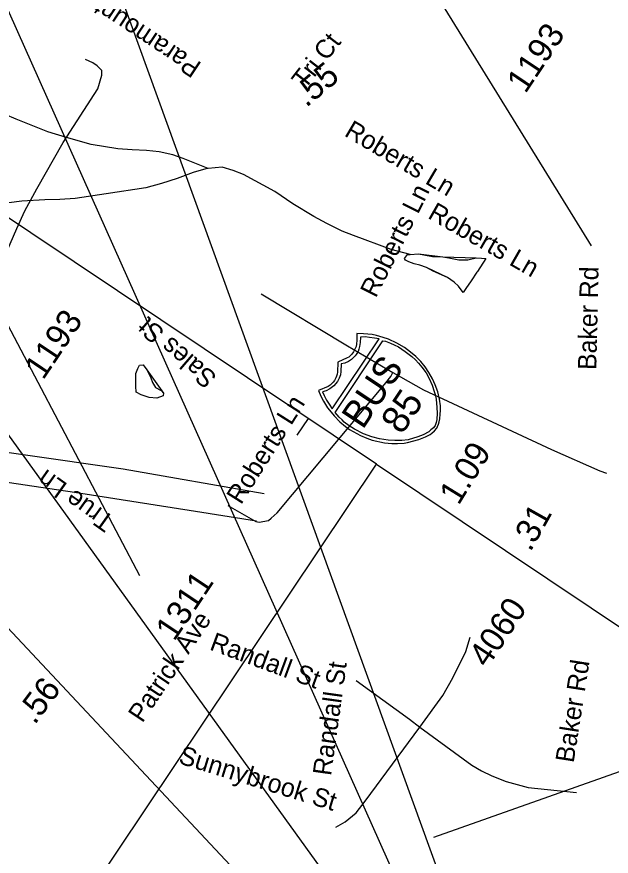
# Model space of a CAD drawing. Extents: x 1716282 to 1717158, y 799307 to 801078.
# Drawn here: x 1716895.7 to 1716939.9, y 800803.5 to 800865.9 of the extents above; entities that cross this region are included whole.
import ezdxf

# ---------------------------------------------------------------- set-up
doc = ezdxf.new("R2010")
doc.units = 0
for name, color, linetype in [('Exist Hydrographic Misc Water Feature', 7, 'Continuous'), ('Exist Road Non-System Type 51', 7, 'Continuous'), ('Exist Road Non-System Type 51 Label', 7, 'Continuous'), ('Exist Road Primary Interstate Mileage Hundredths English Label', 7, 'Continuous'), ('Exist Road Primary Interstate Service Mileage Label', 7, 'Continuous'), ('Exist Road Primary Interstate Shield CELL', 7, 'Continuous'), ('Exist Road Primary Interstate Shield Number Label', 7, 'Continuous'), ('Exist Road Primary Interstate Structure Culvert Number Label', 7, 'Continuous'), ('Exist Road Primary Interstate Structure Ovrhead Sign CELL', 7, 'Continuous'), ('Exist Road Primary US Structure Standard Bridge Number Label', 7, 'Continuous'), ('Exist Road Secondary Mileage Hundredths English Label', 7, 'Continuous'), ('Exist Road Secondary Mileage Tenths English Label', 7, 'Continuous'), ('Exist Road Secondary Structure Standard Bridge Number Label', 7, 'Continuous'), ('Exist Road Secondary Type 51 Attributed', 7, 'Continuous'), ('Exist Road Secondary Type 51 Label', 7, 'Continuous'), ('Exist Road Secondary Type 51 Number Label', 7, 'Continuous'), ('Prop DSN Text', 7, 'Continuous'), ('Prop Road Primary US Projected', 7, 'Continuous')]:
    doc.layers.add(name, color=color, linetype=linetype)

msp = doc.modelspace()

# ---------------------------------------------------------------- linework, layer by layer
at = {"layer": 'Exist Hydrographic Misc Water Feature'}
for points in [[(1716909.97, 800854.633), (1716909.089, 800854.988), (1716908.12, 800855.37), (1716907.335, 800855.66), (1716906.315, 800855.865), (1716905.375, 800855.979), (1716904.322, 800856.032), (1716903.244, 800856.101), (1716901.285, 800856.421), (1716899.432, 800856.948), (1716898.061, 800857.359), (1716895.691, 800858.311), (1716894.897, 800858.641), (1716894.273, 800858.961)], [(1716909.97, 800854.633), (1716909.784, 800854.618), (1716908.856, 800854.339), (1716907.668, 800853.886), (1716906.506, 800853.521), (1716905.336, 800853.197), (1716902.394, 800852.747), (1716900.097, 800852.418), (1716898.947, 800852.328), (1716897.844, 800852.308), (1716896.128, 800852.215), (1716895.153, 800852.073), (1716894.565, 800852.087), (1716893.343, 800852.15), (1716892.531, 800852.246), (1716892.138, 800852.34)], [(1716924.968, 800848.253), (1716923.565, 800848.614), (1716920.759, 800849.651), (1716919.927, 800849.975), (1716918.775, 800850.551), (1716917.822, 800851.059), (1716916.265, 800852.019), (1716914.923, 800852.935), (1716912.58, 800854.185), (1716911.834, 800854.482), (1716911.017, 800854.725), (1716909.97, 800854.633)], [(1716929.933, 800846.932), (1716929.491, 800846.285), (1716929.098, 800845.71), (1716928.902, 800845.423), (1716928.562, 800845.902), (1716928.235, 800846.195), (1716927.733, 800846.54), (1716927.116, 800846.819), (1716926.683, 800847.009), (1716926.196, 800847.272), (1716925.682, 800847.448), (1716925.266, 800847.556), (1716924.864, 800847.69), (1716924.633, 800847.814), (1716924.546, 800847.942), (1716924.782, 800848.238), (1716924.968, 800848.253)], [(1716929.933, 800846.932), (1716929.491, 800846.285), (1716929.098, 800845.71), (1716928.902, 800845.423), (1716928.562, 800845.902), (1716928.235, 800846.195), (1716927.733, 800846.54), (1716926.196, 800847.272), (1716925.682, 800847.448), (1716925.266, 800847.556), (1716924.864, 800847.69), (1716924.633, 800847.814), (1716924.546, 800847.942), (1716924.782, 800848.238), (1716924.968, 800848.253)], [(1716924.968, 800848.253), (1716925.588, 800848.286), (1716926.623, 800848.104), (1716927.404, 800848.065), (1716927.854, 800848.003), (1716928.592, 800847.849), (1716929.259, 800847.85), (1716929.881, 800847.988), (1716930.259, 800847.975), (1716930.597, 800847.956), (1716929.965, 800846.98), (1716929.933, 800846.932)], [(1716924.968, 800848.253), (1716925.588, 800848.286), (1716927.404, 800848.065), (1716929.881, 800847.988), (1716930.259, 800847.975), (1716930.597, 800847.956), (1716929.965, 800846.98), (1716929.933, 800846.932)], [(1716904.625, 800838.014), (1716904.581, 800838.464), (1716904.592, 800839.406), (1716904.734, 800839.768), (1716904.873, 800840.023), (1716905.139, 800840.053), (1716905.417, 800839.688), (1716905.7, 800839.073), (1716905.824, 800838.741), (1716906.061, 800838.368), (1716906.478, 800838.155), (1716906.659, 800837.958), (1716906.617, 800837.743), (1716906.149, 800837.57), (1716905.594, 800837.634), (1716904.994, 800837.834), (1716904.625, 800838.014)], [(1716904.625, 800838.014), (1716904.581, 800838.464), (1716904.592, 800839.406), (1716904.734, 800839.768), (1716904.873, 800840.023), (1716905.139, 800840.053), (1716905.417, 800839.688), (1716906.659, 800837.958), (1716906.617, 800837.743), (1716906.149, 800837.57), (1716905.594, 800837.634), (1716904.994, 800837.834), (1716904.625, 800838.014)]]:
    msp.add_lwpolyline(points, dxfattribs=at)
at = {"layer": 'Exist Road Non-System Type 51'}
for points in [[(1716892.464, 800841.917), (1716892.995, 800843.852), (1716893.84, 800845.849), (1716895.74, 800850.172), (1716896.351, 800851.503), (1716897.24, 800853.126), (1716899.202, 800856.561), (1716901.76, 800860.55), (1716902.066, 800861.573), (1716902.061, 800861.917), (1716901.729, 800862.261), (1716901.388, 800862.489), (1716900.86, 800862.723)], [(1716913.914, 800845.314), (1716920.307, 800841.456), (1716923.671, 800839.488)], [(1716911.428, 800829.608), (1716913.512, 800828.416), (1716913.759, 800828.355), (1716914.436, 800828.498), (1716914.646, 800828.654), (1716915.096, 800829.053), (1716923.061, 800838.6), (1716923.523, 800839.194), (1716923.671, 800839.488)], [(1716923.671, 800839.488), (1716925.951, 800838.188), (1716935.457, 800833.772), (1716939.053, 800832.176), (1716939.562, 800831.999)], [(1716925.686, 800813.132), (1716927.406, 800815.492), (1716928.147, 800816.797), (1716929.097, 800818.757), (1716929.417, 800819.808)], [(1716920.949, 800816.594), (1716924.926, 800813.723), (1716925.686, 800813.132)], [(1716919.455, 800805.699), (1716920.137, 800806.11), (1716920.948, 800806.774), (1716921.627, 800807.639), (1716925.686, 800813.132)], [(1716925.686, 800813.132), (1716929.563, 800810.319), (1716930.268, 800809.895), (1716931.045, 800809.51), (1716932.095, 800809.086), (1716933.725, 800808.654), (1716937.329, 800808.279)]]:
    msp.add_lwpolyline(points, dxfattribs=at)
at = {"layer": 'Exist Road Primary Interstate Shield CELL'}
for points in [[(1716926.941, 800835.336), (1716927.007, 800835.458), (1716927.08, 800835.631), (1716927.131, 800835.813), (1716927.169, 800836.034), (1716927.198, 800836.378), (1716927.215, 800836.659), (1716927.214, 800836.997), (1716927.139, 800837.502), (1716927.019, 800838.037), (1716926.83, 800838.565), (1716926.628, 800839.019), (1716926.358, 800839.48), (1716926.094, 800839.891), (1716925.754, 800840.305), (1716925.399, 800840.666), (1716924.997, 800840.997), (1716924.54, 800841.345), (1716923.981, 800841.671), (1716923.37, 800841.946), (1716922.969, 800842.087), (1716922.471, 800842.227), (1716922.138, 800842.294), (1716921.507, 800842.353), (1716920.999, 800842.366), (1716921.01, 800841.883), (1716920.981, 800841.593), (1716920.952, 800841.423), (1716920.888, 800841.271), (1716920.753, 800841.004), (1716920.642, 800840.853), (1716920.513, 800840.731), (1716920.405, 800840.627), (1716920.289, 800840.56), (1716919.588, 800840.258), (1716919.575, 800839.494), (1716919.552, 800839.347), (1716919.499, 800839.217), (1716919.456, 800839.086), (1716919.343, 800838.898), (1716919.245, 800838.761), (1716919.124, 800838.635), (1716919.025, 800838.538), (1716918.879, 800838.452), (1716918.17, 800838.139), (1716918.337, 800837.718), (1716918.527, 800837.339), (1716918.836, 800836.864), (1716919.094, 800836.525), (1716919.315, 800836.258), (1716919.753, 800835.819), (1716920.159, 800835.473), (1716920.464, 800835.255), (1716921.28, 800834.792), (1716921.75, 800834.6), (1716922.143, 800834.463), (1716923.059, 800834.266), (1716923.609, 800834.211), (1716924.025, 800834.202), (1716924.526, 800834.243), (1716924.777, 800834.279), (1716925.61, 800834.503), (1716926.098, 800834.699), (1716926.446, 800834.883), (1716926.588, 800834.984), (1716926.789, 800835.156)], [(1716918.463, 800838.037), (1716918.579, 800837.768), (1716918.752, 800837.431), (1716918.955, 800837.118), (1716919.187, 800836.782), (1716922.669, 800841.981), (1716922.318, 800842.041), (1716921.96, 800842.093), (1716921.621, 800842.123), (1716921.271, 800842.118), (1716921.259, 800841.704), (1716921.218, 800841.424), (1716921.162, 800841.214), (1716921.098, 800841.048), (1716920.966, 800840.812), (1716920.893, 800840.716), (1716920.613, 800840.45), (1716920.385, 800840.297), (1716920.116, 800840.185), (1716919.853, 800840.125), (1716919.827, 800839.546), (1716919.785, 800839.31), (1716919.698, 800839.063), (1716919.573, 800838.814), (1716919.297, 800838.485), (1716919.015, 800838.271), (1716918.73, 800838.115)], [(1716922.946, 800841.84), (1716923.131, 800841.797), (1716923.508, 800841.656), (1716923.786, 800841.528), (1716924.102, 800841.376), (1716924.589, 800841.03), (1716925.086, 800840.662), (1716925.358, 800840.412), (1716925.592, 800840.164), (1716925.841, 800839.872), (1716926.156, 800839.46), (1716926.373, 800839.038), (1716926.596, 800838.541), (1716926.758, 800838.058), (1716926.823, 800837.852), (1716926.905, 800837.488), (1716926.957, 800836.891), (1716926.979, 800836.466), (1716926.952, 800835.992), (1716926.913, 800835.769), (1716926.821, 800835.54), (1716926.699, 800835.382), (1716926.511, 800835.218), (1716926.359, 800835.085), (1716925.929, 800834.859), (1716925.545, 800834.7), (1716924.831, 800834.484), (1716924.356, 800834.428), (1716923.84, 800834.423), (1716923.333, 800834.451), (1716922.701, 800834.541), (1716922.112, 800834.7), (1716921.514, 800834.93), (1716920.826, 800835.275), (1716920.434, 800835.525), (1716920.078, 800835.797), (1716919.907, 800835.963), (1716919.697, 800836.172), (1716919.387, 800836.516)]]:
    msp.add_lwpolyline(points, close=True, dxfattribs=at)
at = {"layer": 'Exist Road Primary Interstate Structure Culvert Number Label'}
for p, q in [((1716938.452, 800848.887), (1716917.387, 800883.023)), ((1716926.724, 800804.972), (1716957.324, 800815.781))]:
    msp.add_line(p, q, dxfattribs=at)
at = {"layer": 'Exist Road Primary Interstate Structure Ovrhead Sign CELL'}
msp.add_line((1716920.861, 800799.201), (1716870.841, 800868.474), dxfattribs=at)
at = {"layer": 'Exist Road Primary US Structure Standard Bridge Number Label'}
for p, q in [((1716926.584, 800795.95), (1716884.604, 800889.954)), ((1716930.657, 800792.469), (1716901.927, 800871.786)), ((1716921.16, 800792.684), (1716867.42, 800850.005))]:
    msp.add_line(p, q, dxfattribs=at)
at = {"layer": 'Exist Road Secondary Structure Standard Bridge Number Label'}
msp.add_line((1716904.889, 800824.386), (1716880.023, 800871.588), dxfattribs=at)
at = {"layer": 'Exist Road Secondary Type 51 Attributed'}
msp.add_lwpolyline([(1716917.396, 800836.055), (1716916.545, 800834.824)], dxfattribs=at)
at = {"layer": 'Prop DSN Text'}
for points in [[(1716644.267, 800417.02), (1716922.463, 800832.664), (1716560.178, 801075.146), (1716281.982, 800659.503)], [(1716644.267, 800417.02), (1716922.463, 800832.664), (1716967.08, 800802.801), (1716688.884, 800387.158)]]:
    msp.add_lwpolyline(points, close=True, dxfattribs=at)
at = {"layer": 'Prop Road Primary US Projected'}
for points in [[(1716881.402, 800835.489), (1716888.941, 800834.421), (1716903.651, 800832.331), (1716914.115, 800830.484)], [(1716874.271, 800833.772), (1716881.301, 800833.181), (1716890.18, 800832.054), (1716900.03, 800830.579), (1716909.025, 800829.175), (1716913.557, 800828.45)]]:
    msp.add_lwpolyline(points, dxfattribs=at)

# ---------------------------------------------------------------- texts
at = {"layer": 'Exist Road Non-System Type 51 Label'}
for s, rotation, p in [('Paramount St', 146.53214, (1716909.549, 800862.44)), ('Tri Ct', 52.35306, (1716917.153, 800860.457)), ('Roberts Ln', 329.48692, (1716920.007, 800857.098)), ('Roberts Ln', 63.37161, (1716922.422, 800844.962)), ('Roberts Ln', 330.19366, (1716926.206, 800850.989)), ('Sales St', 139.35177, (1716910.693, 800839.223)), ('Roberts Ln', 57.71385, (1716912.404, 800829.607)), ('True Ln', 144.56816, (1716903.094, 800828.675)), ('Patrick Ave', 56.20506, (1716905.075, 800813.39)), ('Randall St', 339.73336, (1716910.001, 800818.916)), ('Randall St', 82.01409, (1716919.089, 800809.478)), ('Sunnybrook St', 342.87848, (1716907.695, 800810.462))]:
    msp.add_text(s, height=1.3775, rotation=rotation, dxfattribs=at).set_placement(p)
at = {"layer": 'Exist Road Primary Interstate Mileage Hundredths English Label'}
msp.add_text('1.09', height=1.8125, rotation=58.36513, dxfattribs=at).set_placement((1716928.568, 800829.559))
at = {"layer": 'Exist Road Primary Interstate Service Mileage Label'}
msp.add_text('.31', height=1.8125, rotation=60.643, dxfattribs=at).set_placement((1716933.902, 800826.101))
at = {"layer": 'Exist Road Primary Interstate Shield Number Label'}
for s, p in [('BUS', (1716921.448, 800835.184)), ('85', (1716924.354, 800834.799))]:
    msp.add_text(s, height=2.03, rotation=56.20506, dxfattribs=at).set_placement(p)
at = {"layer": 'Exist Road Secondary Mileage Hundredths English Label'}
msp.add_text('.56', height=1.8125, rotation=53.23332, dxfattribs=at).set_placement((1716897.08, 800813.255))
at = {"layer": 'Exist Road Secondary Mileage Tenths English Label'}
msp.add_text('.55', height=1.8125, rotation=40.14223, dxfattribs=at).set_placement((1716917.252, 800859.125))
at = {"layer": 'Exist Road Secondary Type 51 Label'}
for rotation, p in [(88.7702, (1716938.8, 800839.662)), (81.07927, (1716937.11, 800810.438))]:
    msp.add_text('Baker Rd', height=1.3775, rotation=rotation, dxfattribs=at).set_placement(p)
at = {"layer": 'Exist Road Secondary Type 51 Number Label'}
for s, p in [('1193', (1716933.534, 800860.143)), ('1193', (1716897.71, 800838.868)), ('1311', (1716907.444, 800819.449)), ('4060', (1716930.707, 800817.476))]:
    msp.add_text(s, height=1.8125, rotation=56.20506, dxfattribs=at).set_placement(p)

doc.saveas('drawing.dxf')
